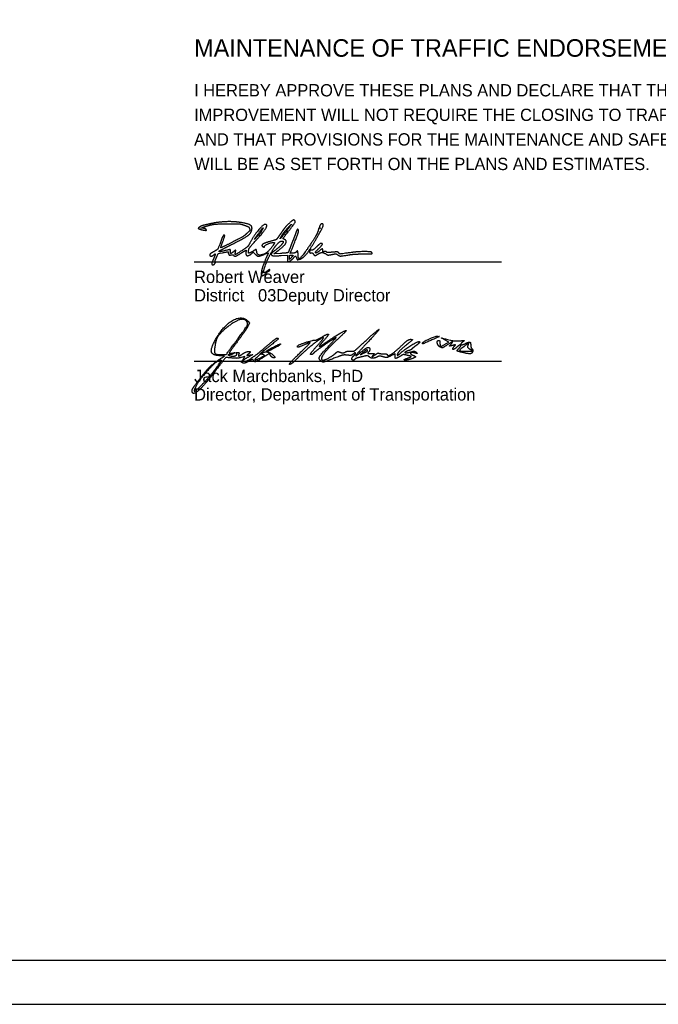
# Model space of a CAD drawing. Extents: x 0 to 34, y 0 to 22.
# Drawn here: x 22.54 to 29.82, y 0 to 11.22 of the extents above; entities that cross this region are included whole.
import ezdxf

# ---------------------------------------------------------------- set-up
doc = ezdxf.new("R2010")
doc.units = 0
for name, color, linetype in [('SH_Border', 7, 'Continuous'), ('SH_Cut_Line', 7, 'Continuous'), ('SH_Data', 7, 'Continuous'), ('SH_Text', 7, 'Continuous')]:
    doc.layers.add(name, color=color, linetype=linetype)

msp = doc.modelspace()

# ---------------------------------------------------------------- linework, layer by layer
at = {"layer": 'SH_Border'}
msp.add_lwpolyline([(1.5, 21.5), (33.5, 21.5), (33.5, 0.5), (1.5, 0.5)], close=True, dxfattribs=at)
at = {"layer": 'SH_Cut_Line'}
msp.add_lwpolyline([(0, 0), (34, 0), (34, 22), (0, 22)], close=True, dxfattribs=at)
at = {"layer": 'SH_Data'}
for p, q in [((24.528, 8.463), (28.028, 8.463)), ((24.528, 7.333), (28.028, 7.333))]:
    msp.add_line(p, q, dxfattribs=at)
at = {"layer": 'SH_Text'}
for p, q in [((24.99, 7.538), (24.99, 7.538)), ((27.129, 7.537), (27.129, 7.537)), ((25.355, 7.448), (25.355, 7.448)), ((25.727, 7.419), (25.727, 7.419)), ((26.504, 7.45), (26.504, 7.45)), ((27.582, 7.431), (27.582, 7.431)), ((25.311, 7.407), (25.311, 7.407))]:
    msp.add_line(p, q, dxfattribs=at)
for points in [[(24.633, 8.845), (24.603, 8.849), (24.63, 8.858)], [(25.249, 8.755), (25.216, 8.719), (25.256, 8.778)], [(24.782, 8.512), (24.803, 8.559), (24.852, 8.568)], [(25.182, 8.556), (25.202, 8.573), (25.223, 8.553)], [(25.331, 8.551), (25.374, 8.568), (25.349, 8.509)], [(25.514, 8.56), (25.435, 8.555), (25.484, 8.592)], [(25.521, 8.536), (25.59, 8.542), (25.59, 8.503)], [(25.662, 8.509), (25.684, 8.533), (25.694, 8.51)], [(25.636, 8.514), (25.613, 8.492), (25.613, 8.512)], [(27.393, 7.528), (27.43, 7.549), (27.389, 7.572)], [(26.453, 7.431), (26.423, 7.405), (26.464, 7.425)], [(27.642, 7.444), (27.698, 7.444), (27.669, 7.467)], [(24.842, 7.371), (24.873, 7.393), (24.835, 7.393)], [(25.085, 7.351), (25.107, 7.384), (25.065, 7.374)]]:
    msp.add_lwpolyline(points, dxfattribs=at)
for points in [[(24.647, 8.883), (24.625, 8.878), (24.599, 8.868), (24.59, 8.861)], [(24.63, 8.858), (24.708, 8.886), (24.802, 8.898), (24.927, 8.898)], [(24.736, 8.903), (24.709, 8.897), (24.669, 8.888), (24.647, 8.883)], [(25.045, 8.914), (24.973, 8.925), (24.809, 8.918), (24.736, 8.903)], [(24.927, 8.898), (25.036, 8.898), (25.059, 8.896), (25.102, 8.881)], [(25.182, 8.816), (25.197, 8.863), (25.145, 8.9), (25.045, 8.914)], [(25.102, 8.881), (25.142, 8.867), (25.153, 8.86), (25.159, 8.843)], [(25.336, 8.891), (25.312, 8.89), (25.202, 8.753), (25.161, 8.674)], [(25.228, 8.704), (25.322, 8.806), (25.37, 8.891), (25.336, 8.891)], [(25.526, 8.76), (25.544, 8.789), (25.583, 8.838), (25.615, 8.872)], [(25.665, 8.941), (25.656, 8.946), (25.569, 8.865), (25.541, 8.825)], [(25.615, 8.872), (25.644, 8.901), (25.628, 8.877), (25.572, 8.804)], [(25.591, 8.796), (25.672, 8.9), (25.686, 8.928), (25.665, 8.941)], [(25.928, 8.741), (25.988, 8.846), (26.006, 8.898), (25.983, 8.898)], [(25.983, 8.898), (25.971, 8.898), (25.953, 8.862), (25.96, 8.851)], [(24.59, 8.861), (24.574, 8.847), (24.574, 8.847), (24.588, 8.839)], [(24.588, 8.839), (24.596, 8.835), (24.618, 8.829), (24.636, 8.826)], [(24.666, 8.831), (24.664, 8.837), (24.649, 8.843), (24.633, 8.845)], [(24.636, 8.826), (24.663, 8.822), (24.669, 8.823), (24.666, 8.831)], [(24.866, 8.768), (24.861, 8.766), (24.847, 8.739), (24.836, 8.708)], [(24.848, 8.676), (24.873, 8.741), (24.879, 8.772), (24.866, 8.768)], [(25.143, 8.801), (25.105, 8.764), (25.056, 8.734), (24.944, 8.678)], [(24.965, 8.666), (25.097, 8.733), (25.172, 8.784), (25.182, 8.816)], [(25.159, 8.843), (25.165, 8.826), (25.163, 8.82), (25.143, 8.801)], [(25.295, 8.814), (25.287, 8.801), (25.266, 8.775), (25.249, 8.755)], [(25.256, 8.778), (25.295, 8.836), (25.322, 8.861), (25.295, 8.814)], [(25.495, 8.759), (25.471, 8.723), (25.46, 8.714), (25.434, 8.708)], [(25.541, 8.825), (25.532, 8.812), (25.512, 8.782), (25.495, 8.759)], [(25.572, 8.804), (25.526, 8.743), (25.499, 8.718), (25.526, 8.76)], [(25.552, 8.722), (25.539, 8.726), (25.542, 8.734), (25.591, 8.796)], [(25.685, 8.79), (25.676, 8.764), (25.662, 8.728), (25.655, 8.712)], [(25.675, 8.692), (25.712, 8.784), (25.722, 8.831), (25.708, 8.836)], [(25.708, 8.836), (25.704, 8.837), (25.694, 8.817), (25.685, 8.79)], [(25.944, 8.832), (25.936, 8.797), (25.895, 8.724), (25.836, 8.638)], [(25.957, 8.848), (25.952, 8.851), (25.946, 8.845), (25.944, 8.832)], [(25.96, 8.851), (25.963, 8.846), (25.962, 8.845), (25.957, 8.848)], [(24.836, 8.708), (24.803, 8.618), (24.793, 8.603), (24.748, 8.578)], [(24.833, 8.624), (24.831, 8.624), (24.838, 8.647), (24.848, 8.676)], [(24.944, 8.678), (24.885, 8.648), (24.835, 8.624), (24.833, 8.624)], [(24.845, 8.606), (24.863, 8.615), (24.917, 8.642), (24.965, 8.666)], [(25.161, 8.674), (25.147, 8.646), (25.123, 8.625), (25.062, 8.585)], [(25.148, 8.58), (25.148, 8.607), (25.169, 8.639), (25.228, 8.704)], [(25.423, 8.645), (25.371, 8.569), (25.247, 8.525), (25.241, 8.58)], [(25.302, 8.656), (25.3, 8.65), (25.303, 8.642), (25.309, 8.639)], [(25.434, 8.708), (25.371, 8.691), (25.306, 8.666), (25.302, 8.656)], [(25.331, 8.642), (25.331, 8.653), (25.433, 8.692), (25.442, 8.683)], [(25.413, 8.58), (25.446, 8.637), (25.506, 8.7), (25.526, 8.7)], [(25.442, 8.683), (25.444, 8.681), (25.436, 8.664), (25.423, 8.645)], [(25.544, 8.693), (25.544, 8.681), (25.494, 8.628), (25.449, 8.594)], [(25.484, 8.592), (25.559, 8.649), (25.589, 8.708), (25.552, 8.722)], [(25.526, 8.7), (25.536, 8.7), (25.544, 8.697), (25.544, 8.693)], [(25.653, 8.563), (25.622, 8.563), (25.62, 8.555), (25.675, 8.692)], [(25.655, 8.712), (25.648, 8.695), (25.633, 8.657), (25.623, 8.628)], [(25.725, 8.492), (25.768, 8.502), (25.848, 8.6), (25.928, 8.741)], [(25.972, 8.674), (25.967, 8.674), (25.944, 8.655), (25.921, 8.633)], [(25.949, 8.617), (25.984, 8.65), (25.994, 8.674), (25.972, 8.674)], [(24.748, 8.578), (24.725, 8.565), (24.706, 8.549), (24.706, 8.543)], [(24.706, 8.543), (24.706, 8.53), (24.737, 8.529), (24.75, 8.542)], [(24.75, 8.542), (24.768, 8.56), (24.768, 8.54), (24.749, 8.498)], [(24.813, 8.584), (24.813, 8.587), (24.827, 8.597), (24.845, 8.606)], [(24.87, 8.59), (24.817, 8.577), (24.813, 8.576), (24.813, 8.584)], [(24.852, 8.568), (24.908, 8.579), (24.924, 8.58), (24.917, 8.574)], [(24.942, 8.582), (24.942, 8.605), (24.935, 8.605), (24.87, 8.59)], [(24.917, 8.574), (24.914, 8.571), (24.916, 8.562), (24.92, 8.554)], [(24.92, 8.554), (24.926, 8.542), (24.933, 8.54), (24.95, 8.543)], [(24.975, 8.578), (24.949, 8.558), (24.942, 8.559), (24.942, 8.582)], [(24.95, 8.543), (24.962, 8.545), (24.974, 8.544), (24.977, 8.54)], [(24.999, 8.575), (25.004, 8.598), (25, 8.598), (24.975, 8.578)], [(24.977, 8.54), (24.986, 8.525), (25.017, 8.533), (25.061, 8.562)], [(25.062, 8.585), (25.007, 8.55), (24.992, 8.547), (24.999, 8.575)], [(25.061, 8.562), (25.086, 8.578), (25.11, 8.593), (25.114, 8.596)], [(25.114, 8.596), (25.12, 8.599), (25.122, 8.594), (25.119, 8.582)], [(25.119, 8.582), (25.112, 8.543), (25.146, 8.528), (25.182, 8.556)], [(25.165, 8.567), (25.151, 8.563), (25.148, 8.565), (25.148, 8.58)], [(25.203, 8.587), (25.191, 8.579), (25.174, 8.57), (25.165, 8.567)], [(25.241, 8.58), (25.238, 8.605), (25.23, 8.606), (25.203, 8.587)], [(25.223, 8.553), (25.249, 8.528), (25.275, 8.527), (25.331, 8.551)], [(25.309, 8.639), (25.324, 8.629), (25.331, 8.63), (25.331, 8.642)], [(25.325, 8.338), (25.313, 8.35), (25.371, 8.509), (25.413, 8.58)], [(25.449, 8.594), (25.426, 8.576), (25.407, 8.557), (25.407, 8.551)], [(25.407, 8.551), (25.407, 8.536), (25.447, 8.531), (25.521, 8.536)], [(25.598, 8.57), (25.596, 8.567), (25.558, 8.563), (25.514, 8.56)], [(25.623, 8.628), (25.612, 8.599), (25.601, 8.572), (25.598, 8.57)], [(25.613, 8.512), (25.613, 8.534), (25.625, 8.544), (25.647, 8.539)], [(25.647, 8.539), (25.657, 8.537), (25.655, 8.532), (25.636, 8.514)], [(25.689, 8.575), (25.683, 8.568), (25.667, 8.563), (25.653, 8.563)], [(25.712, 8.547), (25.712, 8.581), (25.703, 8.592), (25.689, 8.575)], [(25.836, 8.638), (25.754, 8.519), (25.712, 8.488), (25.712, 8.547)], [(25.868, 8.596), (25.854, 8.602), (25.837, 8.574), (25.849, 8.567)], [(25.849, 8.567), (25.853, 8.564), (25.86, 8.565), (25.865, 8.567)], [(25.865, 8.567), (25.869, 8.57), (25.878, 8.565), (25.884, 8.556)], [(25.921, 8.633), (25.895, 8.608), (25.874, 8.594), (25.868, 8.596)], [(25.884, 8.556), (25.898, 8.536), (25.915, 8.536), (25.943, 8.555)], [(25.91, 8.572), (25.91, 8.576), (25.927, 8.596), (25.949, 8.617)], [(25.959, 8.592), (25.935, 8.571), (25.91, 8.561), (25.91, 8.572)], [(25.943, 8.555), (25.968, 8.571), (26.007, 8.569), (26.037, 8.55)], [(25.994, 8.593), (25.994, 8.613), (25.983, 8.613), (25.959, 8.592)], [(26.012, 8.581), (25.997, 8.578), (25.994, 8.58), (25.994, 8.593)], [(26.036, 8.577), (26.033, 8.582), (26.023, 8.584), (26.012, 8.581)], [(26.102, 8.574), (26.06, 8.57), (26.04, 8.571), (26.036, 8.577)], [(26.037, 8.55), (26.05, 8.541), (26.061, 8.541), (26.099, 8.548)], [(26.099, 8.548), (26.138, 8.556), (26.147, 8.556), (26.162, 8.545)], [(26.174, 8.566), (26.164, 8.577), (26.152, 8.578), (26.102, 8.574)], [(26.162, 8.545), (26.184, 8.53), (26.207, 8.53), (26.291, 8.544)], [(26.317, 8.57), (26.195, 8.553), (26.188, 8.553), (26.174, 8.566)], [(26.291, 8.544), (26.326, 8.55), (26.397, 8.554), (26.448, 8.554)], [(26.553, 8.571), (26.547, 8.581), (26.385, 8.58), (26.317, 8.57)], [(26.448, 8.554), (26.539, 8.554), (26.562, 8.557), (26.553, 8.571)], [(24.749, 8.498), (24.738, 8.474), (24.729, 8.45), (24.729, 8.444)], [(24.729, 8.444), (24.729, 8.428), (24.758, 8.432), (24.767, 8.449)], [(24.768, 8.464), (24.764, 8.464), (24.77, 8.485), (24.782, 8.512)], [(24.767, 8.449), (24.772, 8.458), (24.772, 8.464), (24.768, 8.464)], [(25.349, 8.509), (25.317, 8.433), (25.293, 8.354), (25.293, 8.326)], [(25.59, 8.503), (25.59, 8.482), (25.592, 8.464), (25.594, 8.464)], [(25.594, 8.464), (25.605, 8.464), (25.642, 8.488), (25.662, 8.509)], [(25.694, 8.51), (25.702, 8.49), (25.706, 8.487), (25.725, 8.492)], [(25.293, 8.326), (25.293, 8.314), (25.295, 8.304), (25.298, 8.304)], [(25.298, 8.304), (25.308, 8.304), (25.354, 8.334), (25.354, 8.341)], [(25.36, 8.358), (25.342, 8.345), (25.326, 8.336), (25.325, 8.338)], [(25.354, 8.341), (25.354, 8.344), (25.362, 8.351), (25.373, 8.356)], [(25.392, 8.373), (25.392, 8.378), (25.377, 8.371), (25.36, 8.358)], [(25.373, 8.356), (25.383, 8.361), (25.392, 8.369), (25.392, 8.373)], [(24.779, 7.589), (24.865, 7.739), (25.073, 7.855), (25.139, 7.79)], [(25.13, 7.781), (25.104, 7.823), (24.978, 7.781), (24.882, 7.7)], [(24.99, 7.538), (25.111, 7.702), (25.144, 7.758), (25.13, 7.781)], [(25.139, 7.79), (25.158, 7.771), (25.158, 7.766), (25.139, 7.728)], [(24.882, 7.7), (24.816, 7.643), (24.777, 7.579), (24.766, 7.507)], [(25.139, 7.728), (25.128, 7.705), (25.077, 7.629), (25.024, 7.56)], [(25.974, 7.601), (26.052, 7.647), (26.065, 7.634), (26.005, 7.567)], [(26.033, 7.547), (26.113, 7.604), (26.244, 7.681), (26.26, 7.681)], [(26.26, 7.681), (26.265, 7.681), (26.224, 7.639), (26.168, 7.587)], [(26.487, 7.568), (26.562, 7.637), (26.628, 7.694), (26.634, 7.694)], [(26.634, 7.694), (26.639, 7.694), (26.587, 7.634), (26.518, 7.56)], [(24.835, 7.393), (24.737, 7.395), (24.714, 7.476), (24.779, 7.589)], [(24.844, 7.406), (24.891, 7.406), (24.895, 7.41), (24.99, 7.538)], [(25.024, 7.56), (24.972, 7.49), (24.929, 7.43), (24.929, 7.425)], [(25.355, 7.448), (25.376, 7.466), (25.508, 7.532), (25.513, 7.527)], [(25.513, 7.527), (25.519, 7.521), (25.377, 7.444), (25.359, 7.444)], [(25.369, 7.516), (25.419, 7.558), (25.465, 7.594), (25.47, 7.594)], [(25.47, 7.594), (25.495, 7.594), (25.472, 7.569), (25.386, 7.501)], [(26.002, 7.601), (25.992, 7.61), (25.782, 7.443), (25.704, 7.364)], [(25.705, 7.503), (25.705, 7.514), (25.892, 7.577), (25.908, 7.572)], [(25.727, 7.419), (25.798, 7.488), (25.854, 7.544), (25.85, 7.544)], [(25.85, 7.544), (25.847, 7.544), (25.818, 7.533), (25.786, 7.519)], [(26.142, 7.6), (26.093, 7.573), (25.905, 7.44), (25.891, 7.424)], [(25.908, 7.572), (25.914, 7.57), (25.943, 7.583), (25.974, 7.601)], [(25.924, 7.5), (25.97, 7.552), (26.005, 7.597), (26.002, 7.601)], [(26.005, 7.567), (25.977, 7.535), (25.954, 7.505), (25.954, 7.501)], [(25.954, 7.501), (25.954, 7.496), (25.99, 7.517), (26.033, 7.547)], [(25.97, 7.336), (25.944, 7.361), (25.973, 7.411), (26.077, 7.521)], [(26.168, 7.587), (26.069, 7.493), (25.979, 7.385), (25.979, 7.358)], [(26.077, 7.521), (26.123, 7.571), (26.152, 7.606), (26.142, 7.6)], [(26.312, 7.446), (26.345, 7.443), (26.369, 7.459), (26.487, 7.568)], [(26.518, 7.56), (26.388, 7.422), (26.356, 7.375), (26.439, 7.443)], [(26.967, 7.534), (26.893, 7.473), (26.842, 7.419), (26.842, 7.403)], [(26.876, 7.42), (26.93, 7.469), (27.077, 7.559), (27.094, 7.554)], [(26.895, 7.512), (26.94, 7.555), (26.977, 7.581), (26.995, 7.581)], [(26.995, 7.581), (27.019, 7.58), (27.016, 7.574), (26.967, 7.534)], [(27.094, 7.554), (27.102, 7.551), (27.087, 7.532), (27.06, 7.512)], [(27.129, 7.537), (27.129, 7.55), (27.282, 7.62), (27.301, 7.616)], [(27.201, 7.558), (27.138, 7.53), (27.129, 7.527), (27.129, 7.537)], [(27.301, 7.616), (27.322, 7.612), (27.323, 7.613), (27.201, 7.558)], [(27.33, 7.493), (27.304, 7.507), (27.293, 7.569), (27.317, 7.569)], [(27.317, 7.569), (27.324, 7.569), (27.329, 7.555), (27.329, 7.538)], [(27.329, 7.538), (27.329, 7.501), (27.344, 7.499), (27.393, 7.528)], [(27.389, 7.572), (27.346, 7.596), (27.345, 7.596), (27.448, 7.57)], [(27.453, 7.523), (27.477, 7.553), (27.461, 7.549), (27.405, 7.512)], [(27.472, 7.511), (27.439, 7.503), (27.437, 7.504), (27.453, 7.523)], [(27.448, 7.57), (27.469, 7.565), (27.514, 7.562), (27.548, 7.564)], [(27.548, 7.564), (27.603, 7.567), (27.608, 7.565), (27.588, 7.551)], [(27.588, 7.551), (27.559, 7.529), (27.582, 7.513), (27.616, 7.531)], [(27.65, 7.512), (27.66, 7.538), (27.651, 7.535), (27.589, 7.489)], [(27.616, 7.531), (27.656, 7.552), (27.679, 7.547), (27.679, 7.515)], [(24.766, 7.507), (24.754, 7.434), (24.776, 7.406), (24.844, 7.406)], [(24.929, 7.425), (24.929, 7.42), (24.945, 7.42), (24.964, 7.424)], [(24.979, 7.419), (24.969, 7.412), (24.949, 7.406), (24.936, 7.406)], [(24.94, 7.393), (24.97, 7.381), (25.026, 7.406), (25.009, 7.423)], [(24.964, 7.424), (24.989, 7.43), (24.993, 7.429), (24.979, 7.419)], [(25.009, 7.423), (25.004, 7.428), (25.01, 7.431), (25.022, 7.431)], [(25.022, 7.431), (25.037, 7.431), (25.042, 7.425), (25.037, 7.413)], [(25.037, 7.413), (25.028, 7.389), (25.041, 7.389), (25.074, 7.411)], [(25.074, 7.411), (25.102, 7.431), (25.167, 7.448), (25.167, 7.436)], [(25.108, 7.331), (25.131, 7.331), (25.257, 7.42), (25.369, 7.516)], [(25.145, 7.412), (25.126, 7.398), (25.128, 7.397), (25.161, 7.402)], [(25.167, 7.436), (25.167, 7.432), (25.157, 7.421), (25.145, 7.412)], [(25.311, 7.407), (25.293, 7.413), (25.277, 7.408), (25.258, 7.39)], [(25.386, 7.501), (25.292, 7.428), (25.271, 7.407), (25.315, 7.43)], [(25.315, 7.43), (25.328, 7.437), (25.351, 7.439), (25.368, 7.435)], [(25.401, 7.393), (25.384, 7.418), (25.382, 7.417), (25.316, 7.375)], [(25.359, 7.444), (25.354, 7.444), (25.353, 7.446), (25.355, 7.448)], [(25.368, 7.435), (25.404, 7.426), (25.462, 7.369), (25.436, 7.369)], [(25.617, 7.295), (25.607, 7.295), (25.656, 7.351), (25.727, 7.419)], [(25.786, 7.519), (25.723, 7.492), (25.704, 7.488), (25.705, 7.503)], [(25.858, 7.406), (25.848, 7.406), (25.877, 7.448), (25.924, 7.5)], [(25.891, 7.424), (25.883, 7.414), (25.868, 7.406), (25.858, 7.406)], [(25.997, 7.344), (26.019, 7.344), (26.101, 7.389), (26.137, 7.421)], [(26.137, 7.421), (26.157, 7.439), (26.17, 7.442), (26.194, 7.433)], [(26.194, 7.433), (26.214, 7.425), (26.233, 7.426), (26.249, 7.435)], [(26.249, 7.435), (26.262, 7.443), (26.291, 7.447), (26.312, 7.446)], [(26.344, 7.415), (26.329, 7.401), (26.307, 7.396), (26.275, 7.4)], [(26.367, 7.422), (26.367, 7.429), (26.357, 7.426), (26.344, 7.415)], [(26.348, 7.394), (26.358, 7.402), (26.367, 7.415), (26.367, 7.422)], [(26.439, 7.443), (26.487, 7.483), (26.529, 7.493), (26.529, 7.465)], [(26.504, 7.45), (26.504, 7.464), (26.48, 7.455), (26.453, 7.431)], [(26.464, 7.425), (26.486, 7.436), (26.504, 7.447), (26.504, 7.45)], [(26.514, 7.434), (26.503, 7.422), (26.509, 7.419), (26.541, 7.419)], [(26.529, 7.465), (26.529, 7.456), (26.523, 7.442), (26.514, 7.434)], [(26.541, 7.419), (26.578, 7.419), (26.581, 7.417), (26.565, 7.397)], [(26.587, 7.403), (26.608, 7.418), (26.629, 7.427), (26.633, 7.423)], [(26.633, 7.423), (26.637, 7.42), (26.66, 7.416), (26.685, 7.416)], [(26.685, 7.416), (26.709, 7.416), (26.729, 7.411), (26.729, 7.405)], [(26.729, 7.405), (26.729, 7.382), (26.825, 7.443), (26.895, 7.512)], [(26.817, 7.392), (26.817, 7.415), (26.816, 7.415), (26.77, 7.392)], [(26.842, 7.403), (26.842, 7.395), (26.857, 7.403), (26.876, 7.42)], [(26.97, 7.451), (26.921, 7.435), (26.94, 7.422), (26.992, 7.436)], [(27.004, 7.467), (27.001, 7.463), (26.986, 7.456), (26.97, 7.451)], [(26.992, 7.436), (27.03, 7.446), (27.045, 7.445), (27.057, 7.433)], [(27.039, 7.426), (27.002, 7.435), (26.989, 7.412), (27.023, 7.398)], [(27.06, 7.512), (27.033, 7.492), (27.008, 7.472), (27.004, 7.467)], [(27.057, 7.433), (27.07, 7.42), (27.067, 7.419), (27.039, 7.426)], [(27.405, 7.512), (27.365, 7.485), (27.352, 7.482), (27.33, 7.493)], [(27.492, 7.501), (27.507, 7.518), (27.505, 7.519), (27.472, 7.511)], [(27.521, 7.492), (27.489, 7.462), (27.466, 7.469), (27.492, 7.501)], [(27.546, 7.479), (27.577, 7.513), (27.555, 7.524), (27.521, 7.492)], [(27.582, 7.431), (27.527, 7.444), (27.521, 7.452), (27.546, 7.479)], [(27.589, 7.489), (27.546, 7.458), (27.563, 7.444), (27.642, 7.444)], [(27.7, 7.438), (27.692, 7.417), (27.651, 7.415), (27.582, 7.431)], [(27.669, 7.467), (27.649, 7.482), (27.643, 7.495), (27.65, 7.512)], [(27.679, 7.515), (27.679, 7.499), (27.686, 7.48), (27.694, 7.472)], [(27.694, 7.472), (27.701, 7.464), (27.704, 7.449), (27.7, 7.438)], [(24.835, 7.342), (24.814, 7.363), (24.596, 7.137), (24.55, 7.047)], [(24.592, 7.129), (24.669, 7.23), (24.749, 7.307), (24.842, 7.371)], [(24.62, 7.066), (24.687, 7.135), (24.843, 7.334), (24.835, 7.342)], [(24.924, 7.371), (24.89, 7.375), (24.879, 7.364), (24.802, 7.263)], [(24.936, 7.406), (24.913, 7.405), (24.914, 7.404), (24.94, 7.393)], [(25.065, 7.374), (25.025, 7.364), (25.002, 7.364), (24.924, 7.371)], [(25.084, 7.311), (25.066, 7.318), (25.066, 7.322), (25.085, 7.351)], [(25.151, 7.331), (25.125, 7.316), (25.095, 7.307), (25.084, 7.311)], [(25.152, 7.382), (25.101, 7.354), (25.081, 7.331), (25.108, 7.331)], [(25.202, 7.345), (25.199, 7.354), (25.18, 7.348), (25.151, 7.331)], [(25.161, 7.402), (25.198, 7.407), (25.198, 7.407), (25.152, 7.382)], [(25.316, 7.375), (25.248, 7.33), (25.21, 7.321), (25.202, 7.345)], [(25.258, 7.39), (25.213, 7.35), (25.225, 7.341), (25.283, 7.37)], [(25.283, 7.37), (25.329, 7.394), (25.332, 7.399), (25.311, 7.407)], [(25.436, 7.369), (25.426, 7.369), (25.411, 7.38), (25.401, 7.393)], [(25.704, 7.364), (25.667, 7.326), (25.627, 7.294), (25.617, 7.295)], [(26.169, 7.383), (26.023, 7.326), (25.988, 7.317), (25.97, 7.336)], [(25.979, 7.358), (25.979, 7.35), (25.988, 7.344), (25.997, 7.344)], [(26.275, 7.4), (26.246, 7.404), (26.206, 7.398), (26.169, 7.383)], [(26.341, 7.344), (26.323, 7.344), (26.327, 7.377), (26.348, 7.394)], [(26.359, 7.354), (26.356, 7.348), (26.348, 7.344), (26.341, 7.344)], [(26.435, 7.381), (26.397, 7.372), (26.363, 7.36), (26.359, 7.354)], [(26.52, 7.383), (26.509, 7.395), (26.489, 7.394), (26.435, 7.381)], [(26.616, 7.381), (26.585, 7.364), (26.538, 7.366), (26.52, 7.383)], [(26.565, 7.397), (26.553, 7.382), (26.56, 7.384), (26.587, 7.403)], [(26.681, 7.381), (26.654, 7.389), (26.631, 7.389), (26.616, 7.381)], [(26.77, 7.392), (26.732, 7.374), (26.714, 7.371), (26.681, 7.381)], [(26.879, 7.389), (26.834, 7.363), (26.817, 7.363), (26.817, 7.392)], [(26.962, 7.397), (26.923, 7.407), (26.906, 7.406), (26.879, 7.389)], [(26.998, 7.356), (26.951, 7.341), (26.904, 7.347), (26.948, 7.362)], [(26.948, 7.362), (26.962, 7.367), (26.982, 7.374), (26.992, 7.378)], [(26.992, 7.378), (27.003, 7.382), (26.992, 7.39), (26.962, 7.397)], [(27.023, 7.398), (27.054, 7.387), (27.045, 7.372), (26.998, 7.356)], [(24.802, 7.263), (24.65, 7.06), (24.504, 6.932), (24.504, 6.999)], [(24.504, 6.999), (24.504, 7.008), (24.544, 7.067), (24.592, 7.129)], [(24.55, 7.047), (24.518, 6.986), (24.55, 6.994), (24.62, 7.066)]]:
    msp.add_open_spline(points, degree=2, dxfattribs=at)

# ---------------------------------------------------------------- texts
at = {"layer": 'SH_Data'}
for s, p in [('I HEREBY APPROVE THESE PLANS AND DECLARE THAT THE MAKING OF THIS', (24.528, 10.35)), ('IMPROVEMENT WILL NOT REQUIRE THE CLOSING TO TRAFFIC OF THE HIGHWAY', (24.528, 10.07)), ('AND THAT PROVISIONS FOR THE MAINTENANCE AND SAFETY OF TRAFFIC', (24.528, 9.79)), ('WILL BE AS SET FORTH ON THE PLANS AND ESTIMATES.', (24.528, 9.51))]:
    msp.add_text(s, height=0.14, dxfattribs=at).set_placement(p)
at = {"layer": 'SH_Text'}
for s, height, p in [('MAINTENANCE OF TRAFFIC ENDORSEMENT', 0.2, (24.528, 10.802)), ('Robert Weaver', 0.14, (24.528, 8.223)), ('District       Deputy Director', 0.14, (24.528, 8.013)), ('              03', 0.14, (24.528, 8.013)), ('Jack Marchbanks, PhD', 0.14, (24.528, 7.093)), ('Director, Department of Transportation', 0.14, (24.528, 6.883))]:
    msp.add_text(s, height=height, dxfattribs=at).set_placement(p)

doc.saveas('drawing.dxf')
